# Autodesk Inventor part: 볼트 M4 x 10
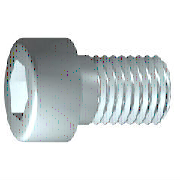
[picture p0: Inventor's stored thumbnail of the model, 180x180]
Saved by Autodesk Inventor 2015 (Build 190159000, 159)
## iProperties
IsCustomPart: 0
Created: 2012-02
Part Number: 볼트 M4 x 10
Material: 스테인리스강
Description: 6각 소켓 머리 캡 나사
Document SubType Name: Modeling
Standard: ISO 4762
Designer: mduedu
Standard Revision: Fourth edition 2004-03-01
Standards Organization: ISO
Language: ko-KR
Size Designation: M4 x 10
Categories: <MemberInstance><Categories><Category DisplayName="조임쇠" InternalName="e4da775c-781d-43d5-af7c-5136215cf5a6" Mnemonic="FSTN"><Category DisplayName="볼트" InternalN
Density: 8.08 g/cm^3
Appearance: 반광택
Mass: 2.09412 g
Surface Area: 3.0572 cm^2
Volume: 0.259174 cm^3
Author: mduedu
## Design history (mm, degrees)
sketch "스케치1"
  geometry: L1 (-1, 0)-(10, 0); L2 (10, 0)-(10, 2); L3 (10, 2)-(1.75, 2); L4 (1.75, 2)-(1.32, 2); L5 (1.32, 2)-(0, 2); L6 (0, 2)-(0, 3.5); L7 (0, 3.5)-(-4, 3.5); L8 (-4, 3.5)-(-4, 1.732); L9 (-4, 1.732)-(-2, 1.732); L10 (-2, 1.732)-(-1, 0); L11 (-6.8, 0)-(12.8, 0) reference; L12 (0, -0.7)-(0, 4.2) reference; L13 (1.75, 2)-(0, 2)
  constraints: 22 end point, 6 parallel, 2 collinear, 2 perpendicular, 1 horizontal, 1 point on line
  dimensions: "d1" = 8.25 distance from line of L3.end L2 (= GEL); "d2" = 0.42952 distance of L4.end L3.end (computed from GAL); "d3" = 4 distance between parallel lines of L8 L6 (= KOH); "d4" = 2 distance of L8.end L9.end (= INTI); "d5" = 60 deg angle of L10 L1; "d6" = 4 diameter of L3 L1 (= GD); "d7" = 4 diameter of L5 L1 (= BDM); "d8" = 3.4641 diameter of L9 L1 (= 1.1547 x SW); "d9" = 7 diameter of L7 L1 (= KOD); "d26" = 10 distance between parallel lines of L12 L2 (= NLG)
revolve "본체" sketch "스케치1" stored, may be unused: angle "d10" = 90 deg
sketch "스케치2"
  geometry: L1 (0, -4.9)-(0, 4.9) reference; L2 (-4.9, 0)-(4.9, 0) reference; L3 (1.732, 0)-(0.866, -1.5); L4 (0.866, -1.5)-(-0.866, -1.5); L5 (-0.866, -1.5)-(-1.732, 0); L6 (-1.732, 0)-(-0.866, 1.5); L7 (-0.866, 1.5)-(0.866, 1.5); L8 (0.866, 1.5)-(1.732, 0); 2 further points
  constraints: 12 end point, 1 coincident, 1 horizontal alignment, 1 point on line, 12 other
extrude "슬롯" join sketch "스케치2" stored distance "d11" = 10; taper "d12" = 0 deg
workplane "Work Plane1"
fillet "Fillet2" dims "d30" = 0.1 (= R)
body "Solid1"
fillet "모깎기1" dims "d17" = 0.4 (= RR)
feature "스레드" dims "d13" = 8.25 (= GEL), "d14" = 0
chamfer "모따기1" distance "d15" = 0.42941 (= -0.5 x SPD + 0.5 x GD); stored, may be unused: second distance "d16" = 0.42941 (= GUL), angle "d27" = 45 deg
other parameters: "GD" = 4 [user parameter; used in 2 equation terms], "NLG" = 10 [user parameter; used in 1 equation term], "GEL" = 8.25 [user parameter; used in 2 equation terms], "KOD" = 7 [user parameter; used in 1 equation term], "KOH" = 4 [user parameter; used in 1 equation term], "INTI" = 2 [user parameter; used in 1 equation term], "GAL" = 0.42941 (= 0.61345 x PTC) [user parameter; used in 1 equation term], "GUL" = 0.42941 (= 0.61345 x PTC) [user parameter; used in 1 equation term], "BDM" = 4 (= NND) [user parameter; used in 1 equation term], "SW" = 3 [user parameter; used in 2 equation terms], "RR" = 0.4 [user parameter; used in 1 equation term], "SPD" = 3.14117 (= NND - 1.2269 x PTC) [user parameter; used in 1 equation term], "d19" = 0, "d28" = 0, "d29" = 0, "R" = 0.1 [user parameter; used in 1 equation term], "TOA" = 30 deg [user parameter], "GD1" = 3.14117 (= THREADDIA - 1.2269 x PTC) [user parameter], "THREADDIA" = 4 [user parameter; used in 1 equation term], "FAWI" = 45 deg [user parameter], "TPU" = 14.28571 (computed from PTC) [user parameter], "PTC" = 0.7 [user parameter; used in 5 equation terms], "NND" = 4 [user parameter; used in 2 equation terms], "E0" = 3.465 (= 1.155 x SW) [user parameter]
